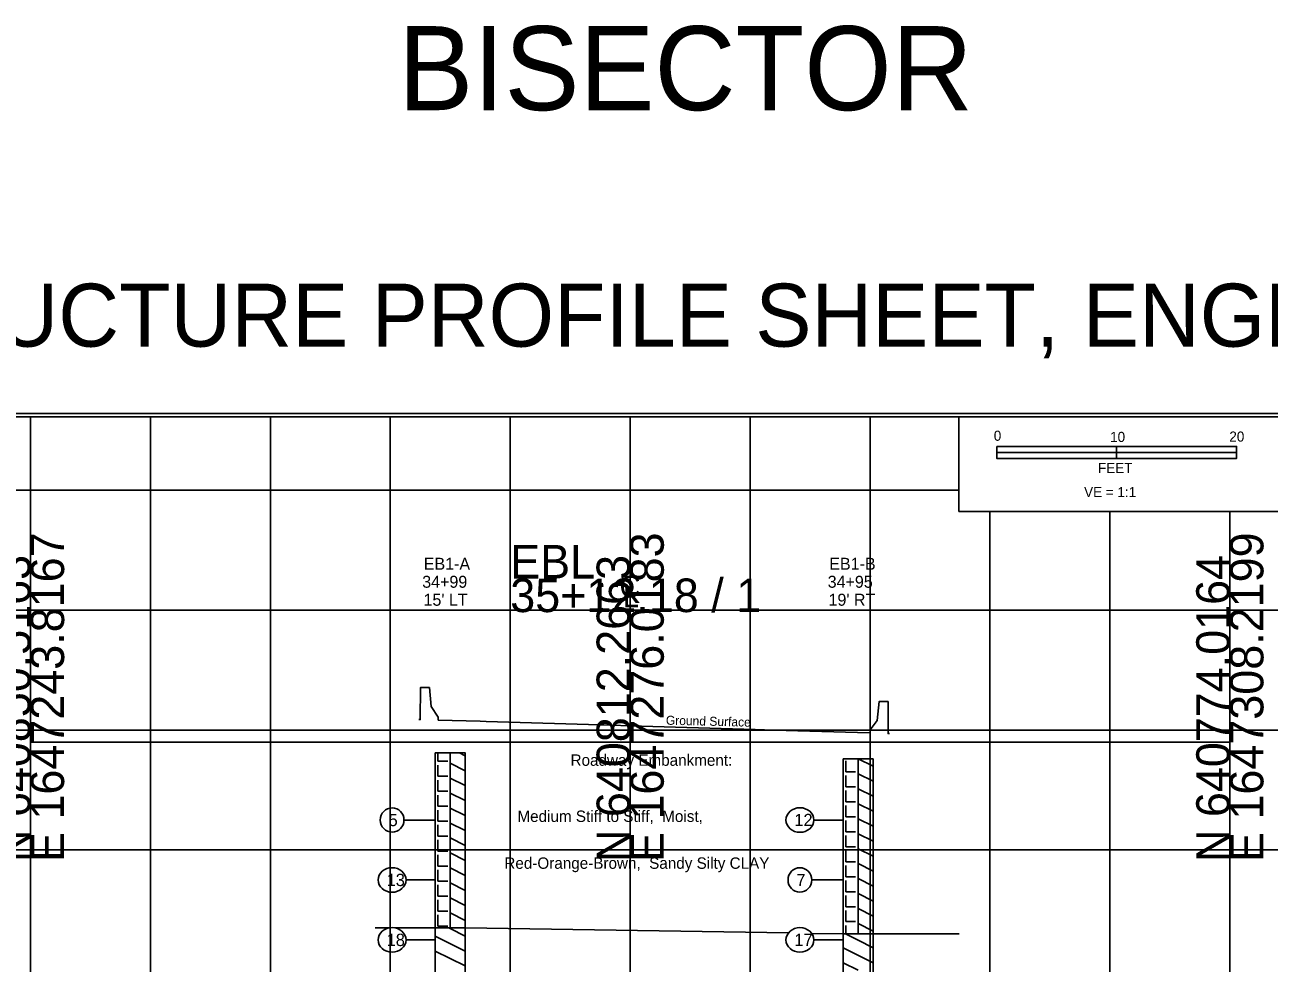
# Model space of a CAD drawing. Extents: x 278618 to 280654, y 171155 to 171855.
# Drawn here: x 280043.7 to 280147.4, y 171248.3 to 171326.6 of the extents above; entities that cross this region are included whole.
import ezdxf

# ---------------------------------------------------------------- set-up
doc = ezdxf.new("R2010")
doc.units = 0
for name, color, linetype in [('Exist XS Ground Line', 7, 'Continuous'), ('Geotech Sheets and Borders Cell', 7, 'Continuous'), ('Misc Plan Tools Cell', 7, 'Continuous'), ('Old_Level_39', 7, 'Continuous'), ('Prop Road Sect_ Boring - Material (Outline)', 7, 'Continuous'), ('Prop Road Sect_ Boring - Peripheral (SPT Oval + Leader)', 7, 'Continuous'), ('Prop Road Sect_ Boring - Peripheral (SPT Tx)', 7, 'Continuous'), ('Prop Road Sect_ Material - Contact (General - Major)', 7, 'Continuous'), ('Prop Road Sect_ Material - Tx (Composite Desc)', 7, 'Continuous'), ('Prop Strc Log_ Log Header Tx', 7, 'Continuous'), ('Prop Strc Sect_ Grid - minor', 7, 'Continuous'), ('Prop Strc Sect_ Misc - User Comment (Tx - small)', 7, 'Continuous'), ('Scratch_Level_2', 7, 'Continuous'), ('Sheet Plot Border Inside CELL', 7, 'Continuous')]:
    doc.layers.add(name, color=color, linetype=linetype)

msp = doc.modelspace()

# ---------------------------------------------------------------- linework, layer by layer
at = {"layer": 'Exist XS Ground Line'}
msp.add_lwpolyline([(280076.5, 171268.63), (280076.62, 171268.62), (280076.63, 171271.29), (280077.38, 171271.29), (280077.54, 171269.71), (280078.12, 171268.83), (280078.12, 171268.58), (280081.6, 171268.47), (280082.12, 171268.46), (280092.54, 171268.15), (280094.12, 171268.1), (280094.12, 171268.1), (280094.12, 171268.1), (280104.54, 171267.79), (280106.12, 171267.74), (280113.07, 171267.53), (280114.12, 171267.5), (280114.13, 171267.75), (280114.71, 171268.54), (280114.87, 171270.12), (280115.62, 171270.12), (280115.62, 171267.45), (280115.75, 171267.45)], dxfattribs=at)
at = {"layer": 'Geotech Sheets and Borders Cell'}
for points in [[(280024.12, 171293.86), (280174.12, 171293.86), (280174.12, 171188.86), (280024.12, 171188.86)], [(280121.53, 171285.96), (280174.12, 171285.96), (280174.12, 171293.86), (280121.53, 171293.86)], [(280124.68, 171291.4), (280144.68, 171291.4), (280144.68, 171290.4), (280124.68, 171290.4)], [(280124.68, 171291.4), (280134.68, 171291.4), (280134.68, 171290.9), (280124.68, 171290.9)], [(280134.68, 171290.9), (280144.68, 171290.9), (280144.68, 171290.4), (280134.68, 171290.4)]]:
    msp.add_lwpolyline(points, close=True, dxfattribs=at)
at = {"layer": 'Misc Plan Tools Cell'}
msp.add_line((280094.12, 171283.77), (280094.12, 171281.16), dxfattribs=at)
at = {"layer": 'Old_Level_39'}
for p, q in [((280094.12, 171266.74), (280094.12, 171280.38)), ((280044.12, 171266.74), (280094.12, 171266.74)), ((280094.12, 171266.74), (280144.12, 171266.74))]:
    msp.add_line(p, q, dxfattribs=at)
at = {"layer": 'Prop Road Sect_ Boring - Material (Outline)'}
for p, q in [((280078.09, 171265.84), (280078.09, 171265.14)), ((280078.09, 171265.84), (280078.09, 171265.14)), ((280079.12, 171265.84), (280079.12, 171263.73)), ((280079.12, 171265.84), (280079.12, 171263.73)), ((280079.89, 171265.84), (280080.37, 171265.6)), ((280079.89, 171265.84), (280080.37, 171265.6)), ((280078.09, 171265.14), (280078.91, 171265.14)), ((280078.09, 171265.14), (280078.91, 171265.14)), ((280078.09, 171264.82), (280078.09, 171263.89)), ((280078.09, 171264.82), (280078.09, 171263.89)), ((280079.12, 171264.98), (280080.37, 171264.35)), ((280079.12, 171264.98), (280080.37, 171264.35)), ((280112.09, 171265.18), (280112.09, 171264.25)), ((280112.09, 171265.18), (280112.09, 171264.25)), ((280113.12, 171265.34), (280113.12, 171262.85)), ((280113.12, 171265.34), (280114.37, 171264.72)), ((280113.12, 171265.34), (280113.12, 171262.85)), ((280113.12, 171265.34), (280114.37, 171264.72)), ((280078.09, 171263.89), (280078.91, 171263.89)), ((280078.09, 171263.89), (280078.91, 171263.89)), ((280079.12, 171263.73), (280079.12, 171261.23)), ((280079.12, 171263.73), (280080.37, 171263.11)), ((280079.12, 171263.73), (280079.12, 171261.23)), ((280079.12, 171263.73), (280080.37, 171263.11)), ((280112.09, 171264.25), (280112.91, 171264.25)), ((280112.09, 171264.25), (280112.91, 171264.25)), ((280112.09, 171263.94), (280112.09, 171263)), ((280112.09, 171263.94), (280112.09, 171263)), ((280113.12, 171264.09), (280114.37, 171263.47)), ((280113.12, 171264.09), (280114.37, 171263.47)), ((280078.09, 171263.57), (280078.09, 171262.64)), ((280078.09, 171263.57), (280078.09, 171262.64)), ((280078.09, 171262.64), (280078.91, 171262.64)), ((280078.09, 171262.64), (280078.91, 171262.64)), ((280112.09, 171263), (280112.91, 171263)), ((280112.09, 171263), (280112.91, 171263)), ((280112.09, 171262.69), (280112.09, 171261.76)), ((280112.09, 171262.69), (280112.09, 171261.76)), ((280113.12, 171262.85), (280113.12, 171260.35)), ((280113.12, 171262.85), (280114.37, 171262.22)), ((280113.12, 171262.85), (280113.12, 171260.35)), ((280113.12, 171262.85), (280114.37, 171262.22)), ((280078.09, 171262.32), (280078.09, 171261.39)), ((280078.09, 171262.32), (280078.09, 171261.39)), ((280079.12, 171262.48), (280080.37, 171261.86)), ((280079.12, 171262.48), (280080.37, 171261.86)), ((280112.09, 171261.76), (280112.91, 171261.76)), ((280112.09, 171261.76), (280112.91, 171261.76)), ((280113.12, 171261.6), (280114.37, 171260.97)), ((280113.12, 171261.6), (280114.37, 171260.97)), ((280078.09, 171261.39), (280078.91, 171261.39)), ((280078.09, 171261.39), (280078.91, 171261.39)), ((280078.09, 171261.07), (280078.09, 171260.14)), ((280078.09, 171261.07), (280078.09, 171260.14)), ((280079.12, 171261.23), (280079.12, 171258.74)), ((280079.12, 171261.23), (280080.37, 171260.61)), ((280079.12, 171261.23), (280079.12, 171258.74)), ((280079.12, 171261.23), (280080.37, 171260.61)), ((280112.09, 171261.44), (280112.09, 171260.51)), ((280112.09, 171261.44), (280112.09, 171260.51)), ((280112.09, 171260.51), (280112.91, 171260.51)), ((280112.09, 171260.51), (280112.91, 171260.51)), ((280078.09, 171260.14), (280078.91, 171260.14)), ((280078.09, 171260.14), (280078.91, 171260.14)), ((280078.09, 171259.83), (280078.09, 171258.89)), ((280078.09, 171259.83), (280078.09, 171258.89)), ((280079.12, 171259.98), (280080.37, 171259.36)), ((280079.12, 171259.98), (280080.37, 171259.36)), ((280112.09, 171260.19), (280112.09, 171259.26)), ((280112.09, 171260.19), (280112.09, 171259.26)), ((280113.12, 171260.35), (280113.12, 171257.85)), ((280113.12, 171260.35), (280114.37, 171259.72)), ((280113.12, 171260.35), (280113.12, 171257.85)), ((280113.12, 171260.35), (280114.37, 171259.72)), ((280078.09, 171258.89), (280078.91, 171258.89)), ((280078.09, 171258.89), (280078.91, 171258.89)), ((280078.09, 171258.58), (280078.09, 171257.65)), ((280078.09, 171258.58), (280078.09, 171257.65)), ((280079.12, 171258.74), (280079.12, 171256.24)), ((280079.12, 171258.74), (280080.37, 171258.11)), ((280079.12, 171258.74), (280079.12, 171256.24)), ((280079.12, 171258.74), (280080.37, 171258.11)), ((280112.09, 171259.26), (280112.91, 171259.26)), ((280112.09, 171259.26), (280112.91, 171259.26)), ((280112.09, 171258.94), (280112.09, 171258.01)), ((280112.09, 171258.94), (280112.09, 171258.01)), ((280113.12, 171259.1), (280114.37, 171258.47)), ((280113.12, 171259.1), (280114.37, 171258.47)), ((280078.09, 171257.65), (280078.91, 171257.65)), ((280078.09, 171257.65), (280078.91, 171257.65)), ((280079.12, 171257.49), (280080.37, 171256.86)), ((280079.12, 171257.49), (280080.37, 171256.86)), ((280112.09, 171258.01), (280112.91, 171258.01)), ((280112.09, 171258.01), (280112.91, 171258.01)), ((280112.09, 171257.69), (280112.09, 171256.76)), ((280112.09, 171257.69), (280112.09, 171256.76)), ((280113.12, 171257.85), (280113.12, 171255.35)), ((280113.12, 171257.85), (280114.37, 171257.23)), ((280113.12, 171257.85), (280113.12, 171255.35)), ((280113.12, 171257.85), (280114.37, 171257.23)), ((280078.09, 171257.33), (280078.09, 171256.4)), ((280078.09, 171257.33), (280078.09, 171256.4)), ((280078.09, 171256.4), (280078.91, 171256.4)), ((280078.09, 171256.4), (280078.91, 171256.4)), ((280112.09, 171256.76), (280112.91, 171256.76)), ((280112.09, 171256.76), (280112.91, 171256.76)), ((280112.09, 171256.44), (280112.09, 171255.51)), ((280112.09, 171256.44), (280112.09, 171255.51)), ((280113.12, 171256.6), (280114.37, 171255.98)), ((280113.12, 171256.6), (280114.37, 171255.98)), ((280078.09, 171256.08), (280078.09, 171255.15)), ((280078.09, 171256.08), (280078.09, 171255.15)), ((280079.12, 171256.24), (280079.12, 171253.74)), ((280079.12, 171256.24), (280080.37, 171255.61)), ((280079.12, 171256.24), (280079.12, 171253.74)), ((280079.12, 171256.24), (280080.37, 171255.61)), ((280112.09, 171255.51), (280112.91, 171255.51)), ((280112.09, 171255.51), (280112.91, 171255.51)), ((280113.12, 171255.35), (280113.12, 171252.86)), ((280113.12, 171255.35), (280114.37, 171254.73)), ((280113.12, 171255.35), (280113.12, 171252.86)), ((280113.12, 171255.35), (280114.37, 171254.73)), ((280078.09, 171255.15), (280078.91, 171255.15)), ((280078.09, 171255.15), (280078.91, 171255.15)), ((280078.09, 171254.83), (280078.09, 171253.9)), ((280078.09, 171254.83), (280078.09, 171253.9)), ((280079.12, 171254.99), (280080.37, 171254.36)), ((280079.12, 171254.99), (280080.37, 171254.36)), ((280112.09, 171255.19), (280112.09, 171254.26)), ((280112.09, 171255.19), (280112.09, 171254.26)), ((280112.09, 171254.26), (280112.91, 171254.26)), ((280112.09, 171254.26), (280112.91, 171254.26)), ((280078.09, 171253.9), (280078.91, 171253.9)), ((280078.09, 171253.9), (280078.91, 171253.9)), ((280078.09, 171253.58), (280078.09, 171252.65)), ((280078.09, 171253.58), (280078.09, 171252.65)), ((280079.12, 171253.74), (280079.12, 171251.24)), ((280079.12, 171253.74), (280080.37, 171253.12)), ((280079.12, 171253.74), (280079.12, 171251.24)), ((280079.12, 171253.74), (280080.37, 171253.12)), ((280112.09, 171253.95), (280112.09, 171253.01)), ((280112.09, 171253.95), (280112.09, 171253.01)), ((280113.12, 171254.1), (280114.37, 171253.48)), ((280113.12, 171254.1), (280114.37, 171253.48)), ((280078.09, 171252.65), (280078.91, 171252.65)), ((280078.09, 171252.65), (280078.91, 171252.65)), ((280078.09, 171252.33), (280078.09, 171251.4)), ((280078.09, 171252.33), (280078.09, 171251.4)), ((280079.12, 171252.49), (280080.37, 171251.87)), ((280079.12, 171252.49), (280080.37, 171251.87)), ((280112.09, 171253.01), (280112.91, 171253.01)), ((280112.09, 171253.01), (280112.91, 171253.01)), ((280112.09, 171252.7), (280112.09, 171251.77)), ((280112.09, 171252.7), (280112.09, 171251.77)), ((280113.12, 171252.86), (280113.12, 171250.74)), ((280113.12, 171252.86), (280114.37, 171252.23)), ((280113.12, 171252.86), (280113.12, 171250.74)), ((280113.12, 171252.86), (280114.37, 171252.23)), ((280078.09, 171251.4), (280078.91, 171251.4)), ((280078.09, 171251.4), (280078.91, 171251.4)), ((280079.01, 171251.24), (280079.12, 171251.19)), ((280079.01, 171251.24), (280079.12, 171251.19)), ((280079.12, 171251.19), (280080.37, 171250.56)), ((280079.12, 171251.19), (280080.37, 171250.56)), ((280112.09, 171251.77), (280112.91, 171251.77)), ((280112.09, 171251.77), (280112.91, 171251.77)), ((280112.09, 171251.45), (280112.09, 171250.74)), ((280112.09, 171251.45), (280112.09, 171250.74)), ((280113.12, 171251.61), (280114.37, 171250.98)), ((280113.12, 171251.61), (280114.37, 171250.98)), ((280077.87, 171250.56), (280080.37, 171249.31)), ((280077.87, 171250.56), (280080.37, 171249.31)), ((280077.87, 171250.56), (280080.37, 171249.31)), ((280077.87, 171250.56), (280080.37, 171249.31)), ((280080.37, 171250.56), (280080.37, 171250.56)), ((280080.37, 171250.56), (280080.37, 171250.56)), ((280080.37, 171250.56), (280080.37, 171250.56)), ((280080.37, 171250.56), (280080.37, 171250.56)), ((280112.07, 171250.74), (280113.12, 171250.22)), ((280112.07, 171250.74), (280113.12, 171250.22)), ((280113.12, 171250.22), (280114.37, 171249.59)), ((280113.12, 171250.22), (280114.37, 171249.59)), ((280077.87, 171249.31), (280079.12, 171248.69)), ((280077.87, 171249.31), (280079.12, 171248.69)), ((280080.37, 171249.31), (280080.37, 171249.31)), ((280080.37, 171249.31), (280080.37, 171249.31)), ((280111.87, 171249.59), (280114.37, 171248.34)), ((280111.87, 171249.59), (280114.37, 171248.34)), ((280111.87, 171249.59), (280114.37, 171248.34)), ((280111.87, 171249.59), (280114.37, 171248.34)), ((280114.37, 171249.59), (280114.37, 171249.59)), ((280114.37, 171249.59), (280114.37, 171249.59)), ((280114.37, 171249.59), (280114.37, 171249.59)), ((280114.37, 171249.59), (280114.37, 171249.59)), ((280079.12, 171248.69), (280080.37, 171248.07)), ((280079.12, 171248.69), (280080.37, 171248.07)), ((280111.87, 171248.34), (280113.12, 171247.72)), ((280111.87, 171248.34), (280113.12, 171247.72)), ((280114.37, 171248.34), (280114.37, 171248.34)), ((280114.37, 171248.34), (280114.37, 171248.34))]:
    msp.add_line(p, q, dxfattribs=at)
for points in [[(280077.87, 171265.84), (280080.37, 171265.84), (280080.37, 171251.24), (280077.87, 171251.24)], [(280111.87, 171265.34), (280114.37, 171265.34), (280114.37, 171250.74), (280111.87, 171250.74)], [(280077.87, 171251.24), (280080.37, 171251.24), (280080.37, 171196.24), (280077.87, 171196.24)], [(280111.87, 171250.74), (280114.37, 171250.74), (280114.37, 171222.74), (280111.87, 171222.74)]]:
    msp.add_lwpolyline(points, close=True, dxfattribs=at)
at = {"layer": 'Prop Road Sect_ Boring - Peripheral (SPT Oval + Leader)'}
for p, q in [((280077.87, 171260.24), (280075.27, 171260.24)), ((280111.87, 171260.24), (280109.43, 171260.24)), ((280077.87, 171255.24), (280075.43, 171255.24)), ((280111.87, 171255.24), (280109.27, 171255.24)), ((280077.87, 171250.24), (280075.43, 171250.24)), ((280111.87, 171250.24), (280109.43, 171250.24))]:
    msp.add_line(p, q, dxfattribs=at)
for centre, major_axis, ratio in [((280074.27, 171260.24), (0, 1.02), 0.966391), ((280108.27, 171260.24), (1.16, 0), 0.883591), ((280074.27, 171255.24), (1.16, 0), 0.883591), ((280108.27, 171255.24), (0, 1.02), 0.966391), ((280074.27, 171250.24), (1.16, 0), 0.883591), ((280108.27, 171250.24), (1.16, 0), 0.883591)]:
    msp.add_ellipse(centre, major_axis=major_axis, ratio=ratio, dxfattribs=at)
at = {"layer": 'Prop Road Sect_ Material - Contact (General - Major)'}
for p, q in [((280074.03, 171251.24), (280072.85, 171251.24)), ((280077.87, 171251.24), (280074.53, 171251.24)), ((280080.37, 171251.24), (280107.31, 171250.82)), ((280109.26, 171250.78), (280111.87, 171250.74)), ((280114.37, 171250.74), (280121.54, 171250.74))]:
    msp.add_line(p, q, dxfattribs=at)
at = {"layer": 'Prop Strc Sect_ Grid - minor'}
for p, q in [((280044.12, 171188.86), (280044.12, 171293.86)), ((280054.12, 171188.86), (280054.12, 171293.86)), ((280064.12, 171188.86), (280064.12, 171293.86)), ((280074.12, 171188.86), (280074.12, 171293.86)), ((280084.12, 171188.86), (280084.12, 171293.86)), ((280094.12, 171188.86), (280094.12, 171293.86)), ((280104.12, 171188.86), (280104.12, 171293.86)), ((280114.12, 171188.86), (280114.12, 171293.86)), ((280121.53, 171287.74), (280024.12, 171287.74)), ((280124.12, 171188.86), (280124.12, 171285.96)), ((280134.12, 171188.86), (280134.12, 171285.96)), ((280144.12, 171188.86), (280144.12, 171285.96)), ((280174.12, 171277.74), (280024.12, 171277.74)), ((280174.12, 171267.74), (280024.12, 171267.74)), ((280174.12, 171257.74), (280024.12, 171257.74))]:
    msp.add_line(p, q, dxfattribs=at)
at = {"layer": 'Sheet Plot Border Inside CELL'}
msp.add_lwpolyline([(280008.61, 171188.58), (280175.37, 171188.58), (280175.37, 171294.14), (280008.61, 171294.14)], close=True, dxfattribs=at)

# ---------------------------------------------------------------- texts
at = {"layer": 'Exist XS Ground Line'}
msp.add_text('Ground Surface', height=0.75, rotation=358.6404, dxfattribs=at).set_placement((280097.09, 171268.19))
at = {"layer": 'Geotech Sheets and Borders Cell'}
for s, p in [('0', (280124.44, 171291.87)), ('20', (280144.08, 171291.8)), ('10', (280134.14, 171291.77)), ('FEET', (280133.13, 171289.18)), ('VE = 1:1', (280131.97, 171287.17))]:
    msp.add_text(s, height=0.84, dxfattribs=at).set_placement(p)
at = {"layer": 'Misc Plan Tools Cell'}
for s, p in [('C', (280093.24, 171278.81)), ('L', (280093.52, 171277.99))]:
    msp.add_text(s, height=1.8, dxfattribs=at).set_placement(p)
at = {"layer": 'Old_Level_39'}
for s, p in [('E 1647243.8167', (280046.92, 171256.74)), ('E 1647276.0183', (280096.92, 171256.74)), ('E 1647308.2199', (280146.92, 171256.74)), ('N 640850.5163', (280044.12, 171256.74)), ('N 640812.2663', (280094.12, 171256.74)), ('N 640774.0164', (280144.12, 171256.74))]:
    msp.add_text(s, height=2.8, rotation=90, dxfattribs=at).set_placement(p)
for s, p in [('EBL', (280084.12, 171280.38)), ('35+12.18 / 1', (280084.12, 171277.58))]:
    msp.add_text(s, height=2.8, dxfattribs=at).set_placement(p)
at = {"layer": 'Prop Road Sect_ Boring - Peripheral (SPT Tx)'}
for s, height, p in [('5', 1.02, (280073.98, 171259.73)), ('12', 1.025, (280107.81, 171259.73)), ('13', 1.025, (280073.81, 171254.73)), ('7', 1.02, (280107.98, 171254.73)), ('18', 1.025, (280073.81, 171249.73)), ('17', 1.025, (280107.81, 171249.73))]:
    msp.add_text(s, height=height, dxfattribs=at).set_placement(p)
at = {"layer": 'Prop Road Sect_ Material - Tx (Composite Desc)'}
for s, p in [('Roadway Embankment:', (280089.15, 171264.76)), ('Medium Stiff to Stiff,  Moist,', (280084.72, 171260.08)), ('Red-Orange-Brown,  Sandy Silty CLAY', (280083.63, 171256.17))]:
    msp.add_text(s, height=0.95, dxfattribs=at).set_placement(p)
at = {"layer": 'Prop Strc Log_ Log Header Tx'}
for s, p in [('EB1-A', (280076.91, 171281.11)), ('EB1-B', (280110.72, 171281.11)), ('34+99', (280076.78, 171279.61)), ('34+95', (280110.59, 171279.61)), ("15' LT", (280076.89, 171278.11)), ("19' RT", (280110.66, 171278.11))]:
    msp.add_text(s, height=1, dxfattribs=at).set_placement(p)
at = {"layer": 'Prop Strc Sect_ Misc - User Comment (Tx - small)'}
msp.add_text('BISECTOR', height=7.009, dxfattribs=at).set_placement((280074.78, 171319.44))
at = {"layer": 'Scratch_Level_2'}
msp.add_text('STRUCTURE PROFILE SHEET, ENGLISH', height=5.25, dxfattribs=at).set_placement((280027.32, 171299.72))

doc.saveas('drawing.dxf')
